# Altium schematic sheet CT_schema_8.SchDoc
size 423 x 414 mm
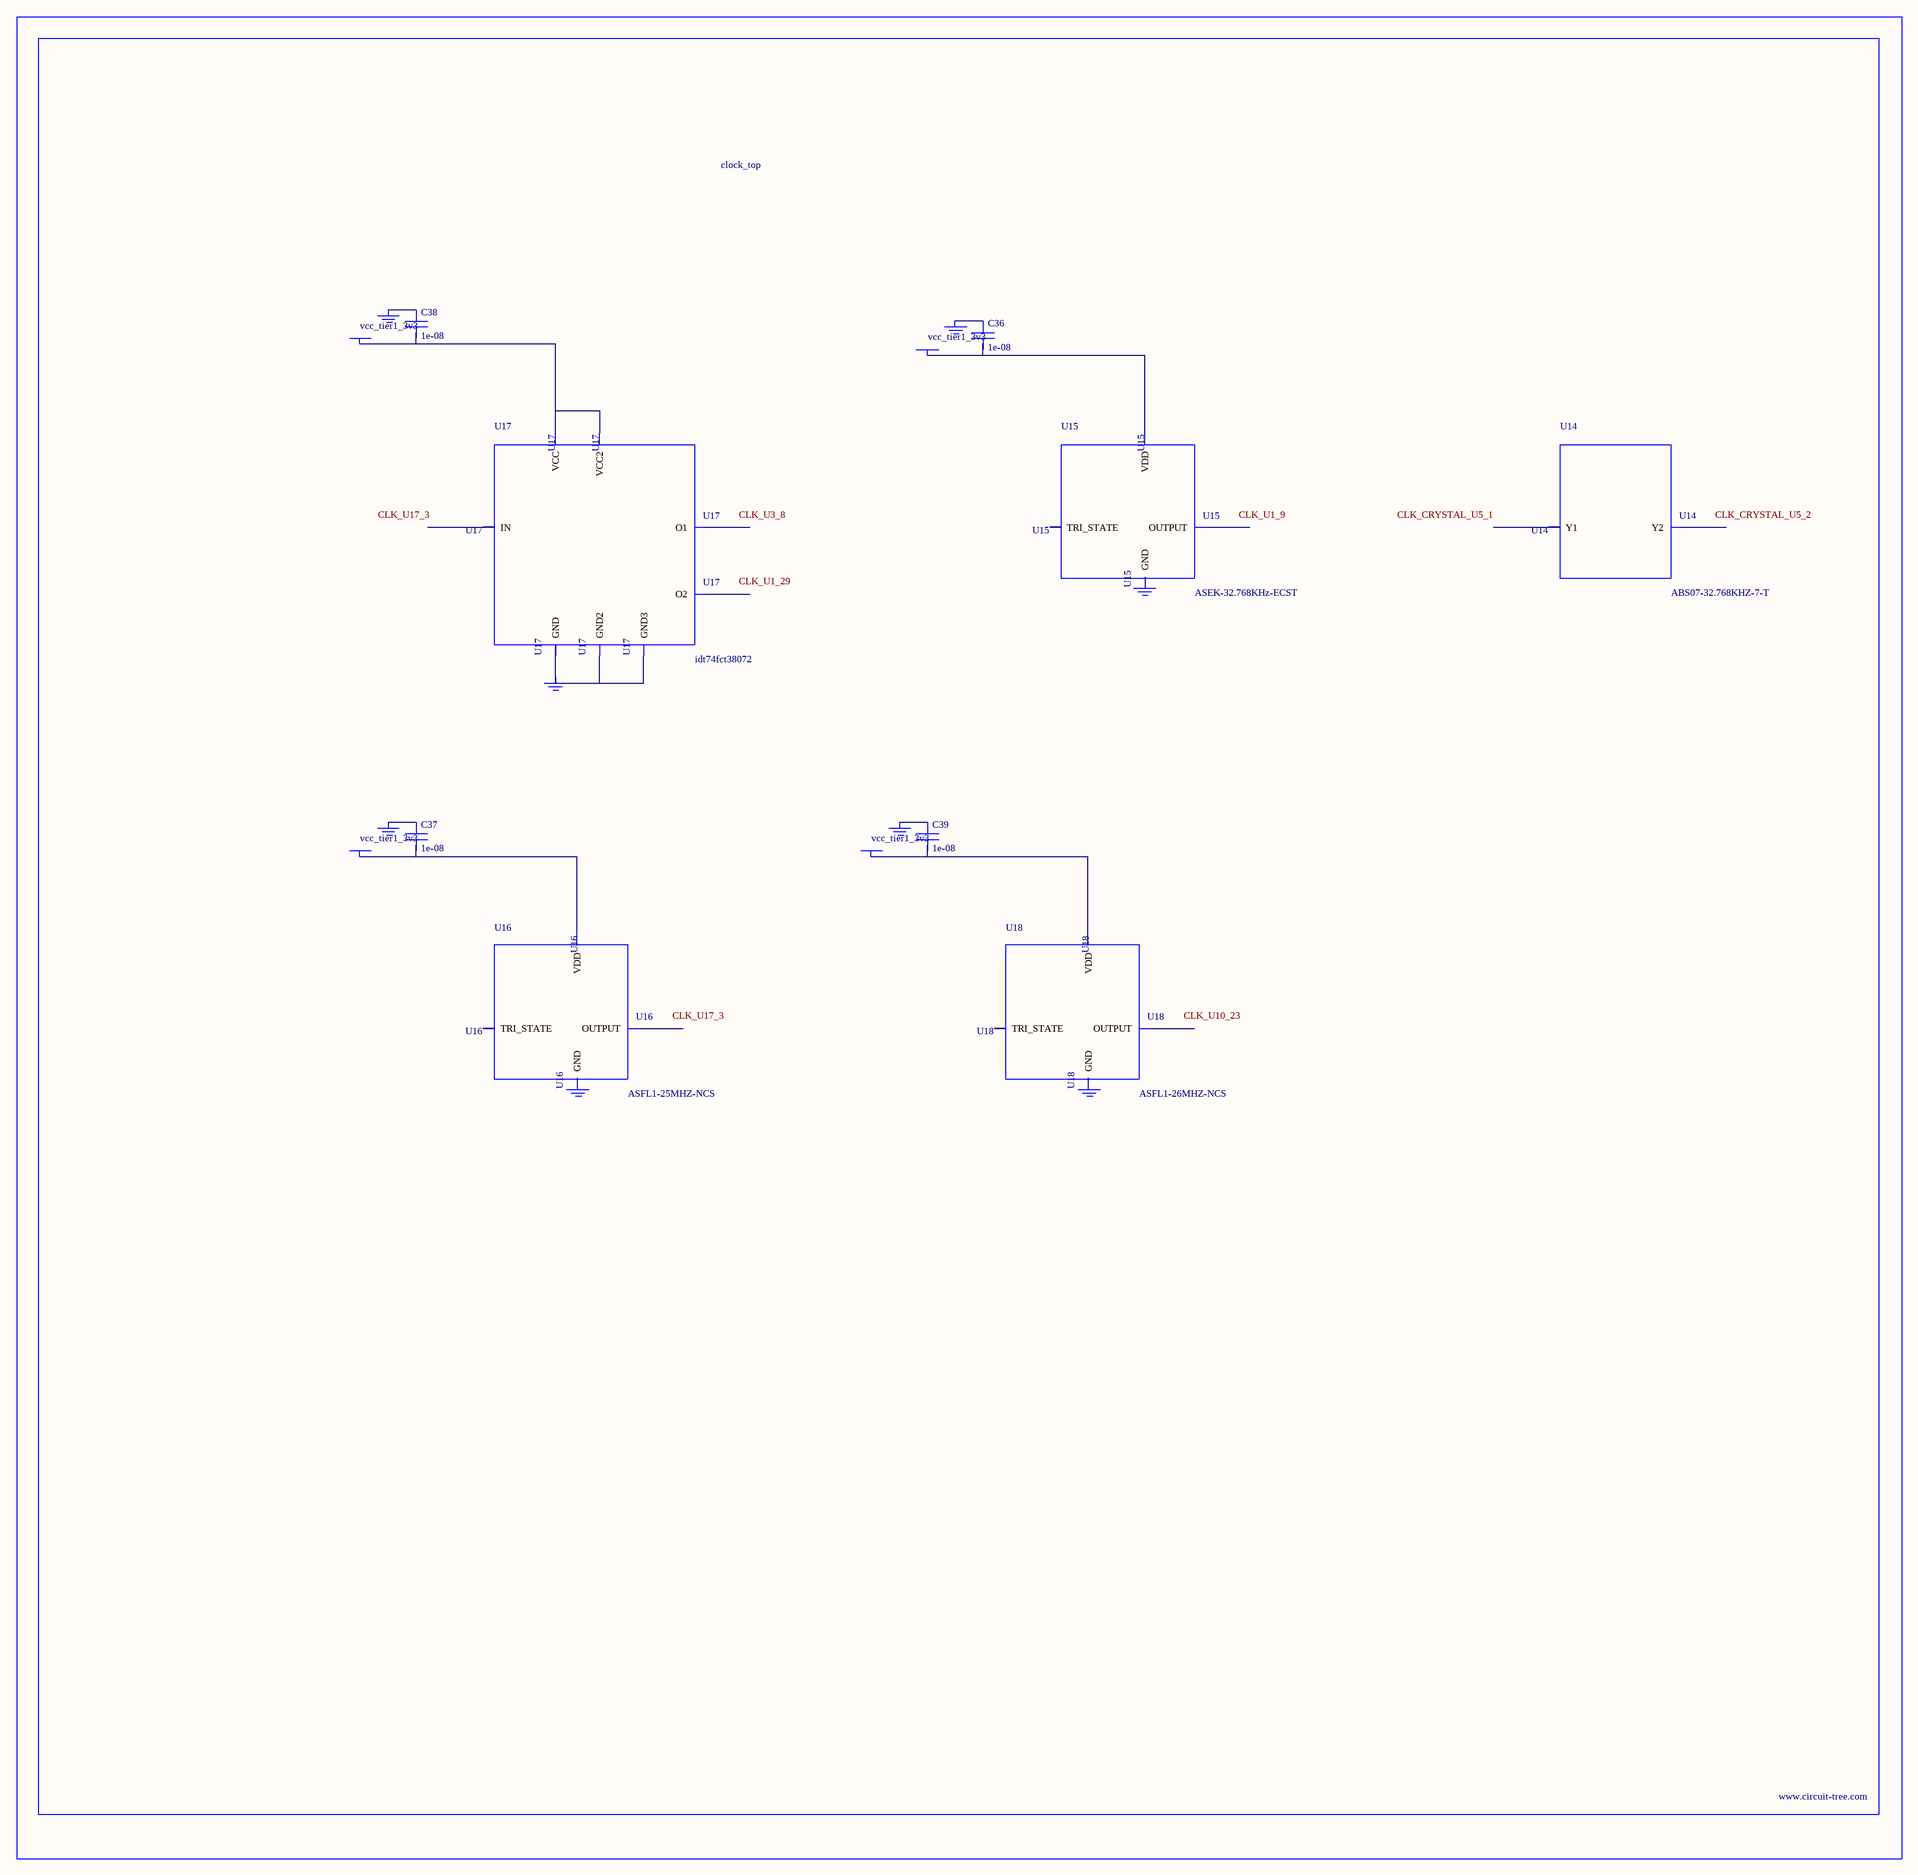
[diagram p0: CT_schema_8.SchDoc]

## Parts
BORDER7  (no value)
C36  1e-08  [C0402]
C37  1e-08  [C0402]
C38  1e-08  [C0402]
C39  1e-08  [C0402]
GND_INSTANCE_7_0  (no value)
GND_INSTANCE_7_1  (no value)
GND_INSTANCE_7_2  (no value)
GND_INSTANCE_7_3  (no value)
GND_INSTANCE_7_4  (no value)
GND_INSTANCE_7_5  (no value)
GND_INSTANCE_7_6  (no value)
GND_INSTANCE_7_7  (no value)
POWER_INSTANCE_7_0  vcc_tier1_3v3
POWER_INSTANCE_7_1  vcc_tier1_3v3
POWER_INSTANCE_7_2  vcc_tier1_3v3
POWER_INSTANCE_7_3  vcc_tier1_3v3
U14  ABS07-32.768KHZ-7-T  [ABS07-32.768KHZ-7-T]
U15  ASEK-32.768KHz-ECST  [ASEK]
U16  ASFL1-25MHZ-NCS  [ASFL1]
U17  idt74fct38072  [IDT74FCT38072]
U18  ASFL1-26MHZ-NCS  [ASFL1]

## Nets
NetC36_1: C36.1 GND_INSTANCE_7_0.0(GND)
NetC36_2: C36.2 POWER_INSTANCE_7_0.0(PWR) U15.4(VDD)
NetC37_1: C37.1 GND_INSTANCE_7_2.0(GND)
NetC37_2: C37.2 POWER_INSTANCE_7_1.0(PWR) U16.4(VDD)
NetC38_1: C38.1 GND_INSTANCE_7_4.0(GND)
NetC38_2: C38.2 POWER_INSTANCE_7_2.0(PWR) U17.1(VCC) U17.2(VCC2)
NetC39_1: C39.1 GND_INSTANCE_7_6.0(GND)
NetC39_2: C39.2 POWER_INSTANCE_7_3.0(PWR) U18.4(VDD)
NetGND_INSTANCE_7_5_0: GND_INSTANCE_7_5.0(GND) U17.4(GND) U17.5(GND2) U17.8(GND3)

Not connected (* = marked no-connect by the designer): GND_INSTANCE_7_1 0(GND); GND_INSTANCE_7_3 0(GND); GND_INSTANCE_7_7 0(GND); U14 1(Y1) 2(Y2); U15 1(TRI_STATE) 2(GND) 3(OUTPUT); U16 1(TRI_STATE) 2(GND) 3(OUTPUT); U17 3(IN) 6(O2) 7(O1); U18 1(TRI_STATE) 2(GND) 3(OUTPUT)

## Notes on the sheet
- Labels drawn without touching a wire or pin: CLK_CRYSTAL_U5_1, CLK_CRYSTAL_U5_2, CLK_U1_9, CLK_U1_29, CLK_U3_8, CLK_U10_23, CLK_U17_3

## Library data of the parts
BORDER7 = BORDER_PAGE7
C36-C39 = C0402C103K3RAC
GND_INSTANCE_7_0-GND_INSTANCE_7_7 = GND
POWER_INSTANCE_7_0-POWER_INSTANCE_7_3 = PWR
